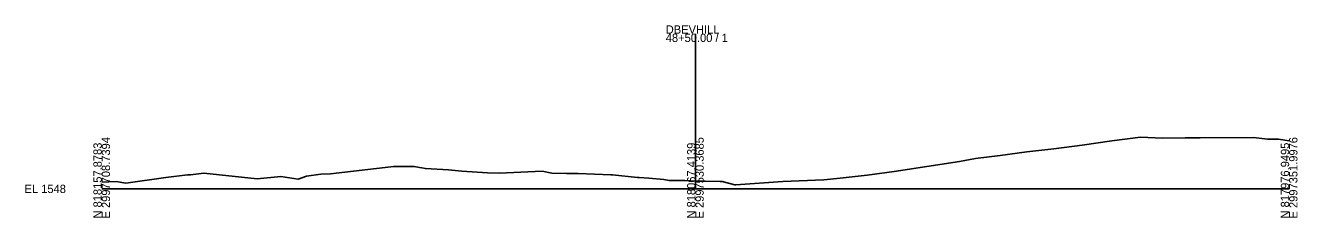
# Model space of a CAD drawing. Extents: x -26 to 2003, y -10 to 2160.
# Drawn here: x -25.7 to 402.8, y 490.3 to 555.2 of the extents above; entities that cross this region are included whole.
import ezdxf

# ---------------------------------------------------------------- set-up
doc = ezdxf.new("R2010")
doc.units = 0
doc.layers.add('DESIGN - SHEET - Light Grid', color=7, linetype='Continuous')
doc.layers.add('SURVEY - GROUND - Top of Ground', color=7, linetype='Continuous')

msp = doc.modelspace()

# ---------------------------------------------------------------- linework, layer by layer
at = {"layer": 'DESIGN - SHEET - Light Grid'}
for p, q in [((200, 500), (200, 552.38)), ((0, 500), (200, 500)), ((200, 500), (400, 500))]:
    msp.add_line(p, q, dxfattribs=at)
at = {"layer": 'SURVEY - GROUND - Top of Ground'}
msp.add_lwpolyline([(0, 502.25), (4.83, 502.5), (8.16, 501.92), (21.64, 503.8), (28.92, 504.7), (29.94, 504.74), (34.37, 505.3), (52.38, 503.35), (60.32, 504.15), (66.22, 503.23), (68.97, 504.32), (73.84, 504.99), (77.05, 505.05), (97.37, 507.42), (98.26, 507.54), (105.3, 507.54), (107.08, 507.24), (107.83, 507.12), (109.06, 506.84), (116.81, 506.47), (121.33, 506.01), (130, 505.4), (133.97, 505.36), (148.35, 506.02), (151.64, 505.34), (156.53, 505.24), (160.54, 505.17), (171.48, 504.73), (172.09, 504.74), (180.45, 503.81), (181.01, 503.81), (184.27, 503.67), (189.41, 503.14), (191.14, 502.78), (196.44, 502.79), (200.13, 502.65), (203.24, 502.6), (208.31, 502.48), (208.97, 502.47), (213.25, 501.32), (213.62, 501.37), (229.45, 502.46), (243.25, 503.08), (248.81, 503.66), (257.8, 504.62), (266.95, 505.92), (288.92, 509.24), (294.32, 510.2), (302.69, 511.27), (311.63, 512.47), (320.77, 513.49), (330.3, 514.7), (340.33, 516.24), (349.92, 517.46), (357.37, 517.16), (365.03, 517.25), (366.51, 517.2), (370.04, 517.23), (387.99, 517.3), (392.68, 516.83), (396, 516.76), (396.47, 516.78), (398.58, 516.46), (400, 516.25)], dxfattribs=at)

# ---------------------------------------------------------------- texts
at = {"layer": 'DESIGN - SHEET - Light Grid'}
for s, p in [('DBEVHILL', (190, 552.38)), ('48+50.00 / 1', (190, 549.58)), ('EL 1548', (-26, 498.6))]:
    msp.add_text(s, height=2.8, dxfattribs=at).set_placement(p)
for s, p in [('N 818157.8783', (0, 490)), ('E 2997708.7394', (2.8, 490)), ('N 818067.4139', (200, 490)), ('E 2997530.3685', (202.8, 490)), ('N 817976.9495', (400, 490)), ('E 2997351.9976', (402.8, 490))]:
    msp.add_text(s, height=2.8, rotation=90, dxfattribs=at).set_placement(p)

doc.saveas('drawing.dxf')
